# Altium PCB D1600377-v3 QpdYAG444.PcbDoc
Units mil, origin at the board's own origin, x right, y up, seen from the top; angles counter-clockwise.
Board outline 1290.19 x 1000 mil, 2 copper layers (Top Layer, Bottom Layer); 1 components, 0 nets, 18 pads, 0 vias.
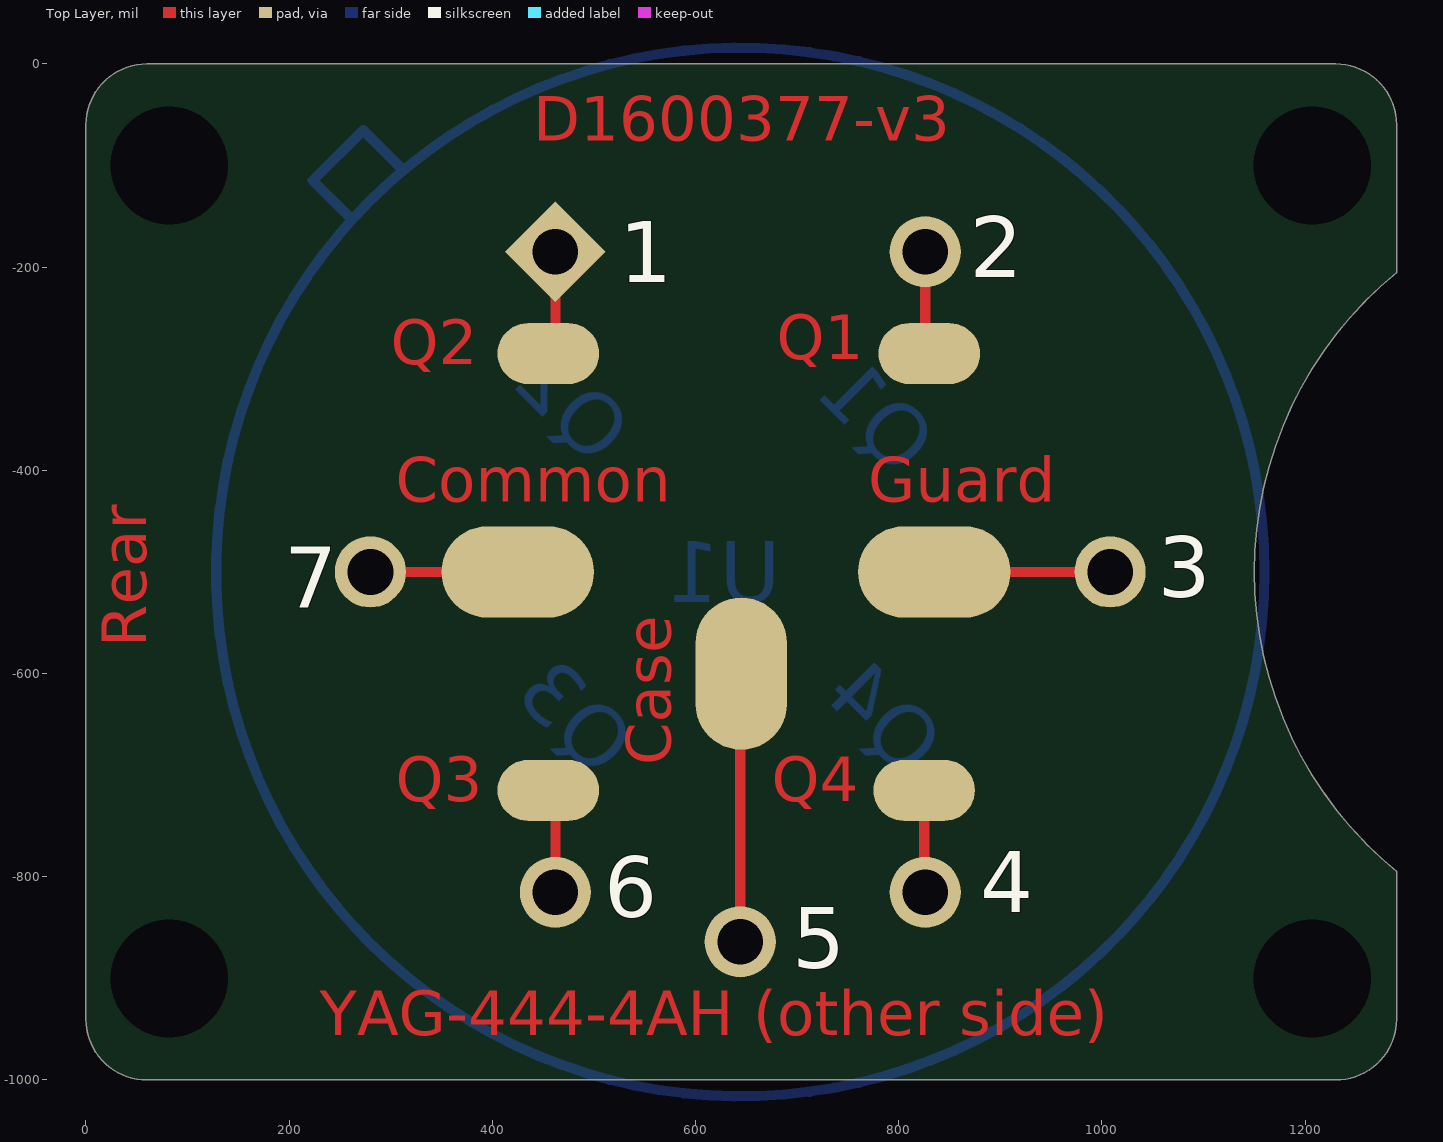
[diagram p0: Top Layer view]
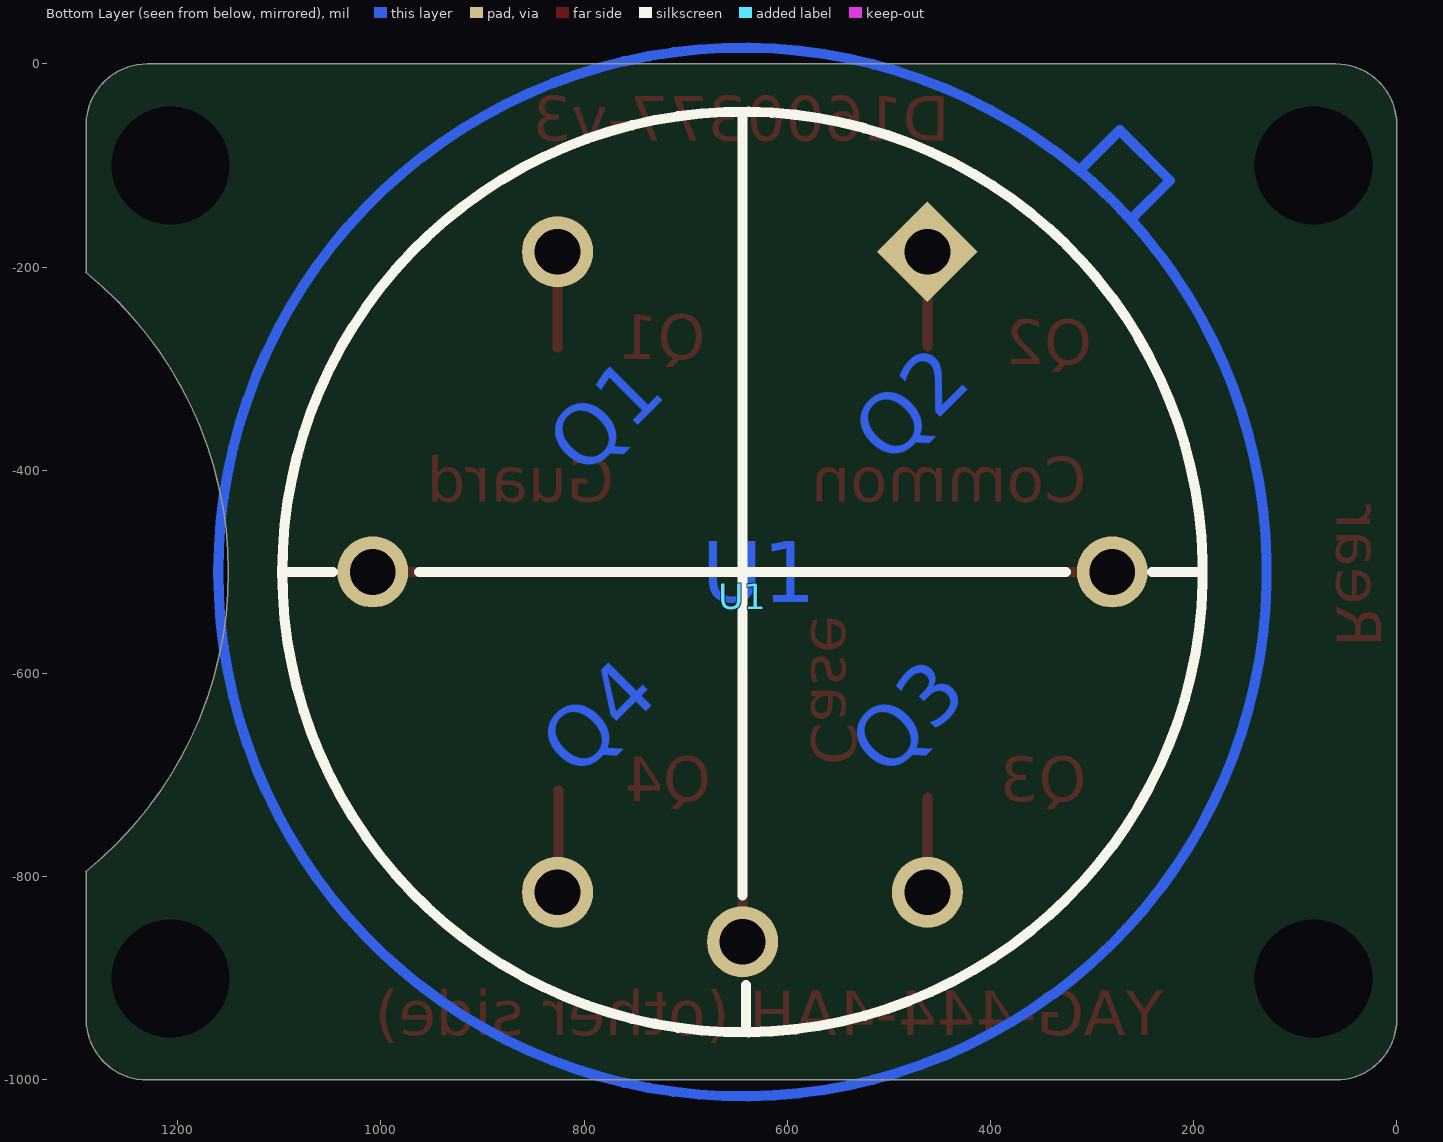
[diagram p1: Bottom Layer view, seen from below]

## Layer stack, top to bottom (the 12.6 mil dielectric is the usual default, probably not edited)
Top Solder: solder mask 0.4, Solder Resist, Dk 3.5
Top Layer: signal copper 1.4
Dielectric1: dielectric 12.6, FR-4, Dk 4.8
Bottom Layer: signal copper 1.4
Bottom Solder: solder mask 0.4, Solder Resist, Dk 3.5

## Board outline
0,-940 ccw(c60,-940) 60,-1000 1230,-1000 ccw(c1230,-940) 1290,-940 1290,-794.77 1290.19,-794.77 cw(c1530,-500) 1290.19,-205.23 1290,-205.23 1290,-60 ccw(c1230,-60) 1230,0 60,0 ccw(c60,-60) 0,-60

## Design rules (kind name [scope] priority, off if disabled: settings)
Clearance [All] p1: gap=10 ignorepadtopadclearanceinfootprint=FALSE
PolygonConnect [All] p1: connectstyle=Relief reliefconductorwidth=10 reliefentries=4 polygonreliefangle="90 Angle" airgapwidth=10
RoutingVias [All] p1: holewidth=28 width=50 viastyle="Through Hole" minholewidth=28 minwidth=50 maxholewidth=28 maxwidth=50
SilkToSolderMaskClearance SilkscreenOverComponentPads [IsPad] p1: minsilkscreentomaskgap=10 clearancetoexposedcopper=TRUE
SolderMaskExpansion [All] p1: expansion=4 istentingtop=FALSE
Width [All] p1: maxlimit=10 minlimit=10 preferedwidth=10
29 further rules are at their usual default settings.

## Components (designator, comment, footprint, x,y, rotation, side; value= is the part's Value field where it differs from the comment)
U1 "Photodiode" YAG444-4 644,-500 r270 bottom

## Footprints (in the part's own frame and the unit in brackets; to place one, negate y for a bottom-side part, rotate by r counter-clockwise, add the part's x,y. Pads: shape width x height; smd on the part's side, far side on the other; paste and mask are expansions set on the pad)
YAG444-4 [mil]
  rect 70x70 hole 45 rot 135: 1(-315.23,182)
  round 70 hole 45: 2(-315.23,-182) 3(0,-364) 4(315.23,-182) 5(364,0) 6(315.23,182) 7(0,364)
  Top Layer circle w10: c0,0 r516
  Top Layer lines w10: -350.02,385.37 -385.37,420.73 -434.87,371.23 -395.98,332.34
  silkscreen extent -453,-453 453,453

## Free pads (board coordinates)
  round 60 hole 116 unplated: 0(82,-100) 1(1207,-100) 2(82,-900) 3(1207,-900)
  oval 100x60 smd: 1(455,-285) 2(830,-285) 4(825,-715) 6(455,-715)
  oval 150x90 smd: 3(835,-500) 7(425,-500)
  oval 90x150 smd: 5(645,-600)

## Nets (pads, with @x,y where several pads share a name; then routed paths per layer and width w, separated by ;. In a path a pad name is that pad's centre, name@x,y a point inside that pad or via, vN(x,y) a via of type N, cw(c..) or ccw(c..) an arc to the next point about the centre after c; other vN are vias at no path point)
pads on no net: U1.1 U1.2 U1.3 U1.4 U1.5 U1.6 U1.7
copper on no net: | length 961.9
  Top Layer w10: 280,-500 425,-500 ; 462,-815.23 462,-722 ; 462,-278 462,-184.77 ; 644,-864 644,-600 ; 825,-814.23 825,-715 ; 826,-279 826,-184.77 ; 835,-500 1008,-500

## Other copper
Top Layer:
  text "D1600377-v3" at 440,-90 h75
  text "Q1" at 680,-305 h75
  text "Q2" at 300,-310 h75
  text "Common" at 305,-445 h75
  text "Guard" at 770,-445 h75
  text "Rear" at 73.63,-574.08 h75 r90
  text "Case" at 590,-690 h75 r90
  text "Q3" at 305,-740 h75
  text "Q4" at 675,-740 h75
  text "YAG-444-4AH (other side)" at 230,-970 h75

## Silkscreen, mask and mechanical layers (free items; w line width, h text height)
Top Overlay:
  text "2" at 870,-210 h60
  text "1" at 525,-215 h60
  text "3" at 1055,-525 h60
  text "7" at 195,-535 h60
  text "4" at 880,-835 h60
  text "6" at 510,-840 h60
  text "5" at 695,-890 h60
Mechanical 1:
  lines w10: 1290,-794.77 1290,-940 cw(c1230,-940) 1230,-1000 60,-1000 cw(c60,-940) 0,-940 0,-60 cw(c60,-60) 60,0 1230,0 cw(c1230,-60) 1290,-60 1290,-205.23 ; 1290.19,-794.77 cw(c1530,-500) 1290.19,-205.23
